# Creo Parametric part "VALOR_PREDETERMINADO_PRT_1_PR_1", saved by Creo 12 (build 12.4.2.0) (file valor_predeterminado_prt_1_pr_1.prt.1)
Units: Custom; MM, KILOGRAM, SECS

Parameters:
  PTC_WM_ITERATION = "0"
  PTC_WM_VERSION = "-.0"
  PTC_WM_LIFECYCLE_STATE = "In Work"
  PTC_WM_LIFECYCLE = "MO_CADDocument"
  PTC_WM_CREATED_BY = "Maximilian Roepper (Z0017RMS: MO)"
  PTC_WM_CREATED_ON = "18-Sep-26 11:36:42 AM"
  PTC_WM_MODIFIED_BY = "Maximilian Roepper (Z0017RMS: MO)"
  PTC_WM_MODIFIED_ON = "18-Sep-26 11:36:46 AM"
  PDMLINKNUMBER = "PDM000071455078"
  PTC_WM_NAME = "valor_predeterminado_prt_1_pr_1.prt"
  PTC_WM_NUMBER = "PDM000071455078"

Other parameters: WEIGHT, WEIGHT_FACTOR, WEIGHT_ADD, _MASS_TEMP, _DIFF_TEMP, MC_ERRORS, SUPPLIER

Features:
  1. coordinate system
  2. datum plane "PRT_YZ"
  3. datum plane "PRT_XY"
  4. datum plane "PRT_XZ"
  5. coordinate system
  6. datum axis
  7. datum axis
  8. datum axis
  9. coordinate system
  10. imported feature
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
Other named items: PRT, SIEMENS_MO, DRW_VIEW_ORG, PRT_X, PRT_Y, PRT_Z, CS0, ROUGH_GROB

Layers: 00_STD_CSYS-KSYS, 01_STD_PLANES-EBENEN, 02_STD_AXES-ACHSEN, 03_STD_CSYS-KSYS, 24_IMPORT_FEAT-IMPORT_KE

Surfaces: 41 tabulated cylinder, 30 plane, 20 cylinder, 8 torus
